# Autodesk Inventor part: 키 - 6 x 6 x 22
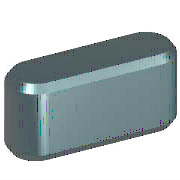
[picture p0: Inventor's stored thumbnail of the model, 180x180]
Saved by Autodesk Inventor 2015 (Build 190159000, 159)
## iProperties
IsCustomPart: 1
Created: 2012-02
Part Number: 키 - 6 x 6 x 22
Material: 강철, 연강
Description: 키 및 해당 키홈
Document SubType Name: Modeling
Standard: KS B 1311
Designer: mduedu
Standards Organization: KS
Language: ko-KR
Size Designation: 6 x 6 x 22
Categories: <MemberInstance><Categories><Category DisplayName="샤프트 부품" InternalName="7f7aeb1f-a693-4053-b835-cee3144e0d98" Mnemonic="SHFT"><Category DisplayName="키" Interna
Density: 7.86 g/cm^3
Mass: 5.79788 g
Surface Area: 5.294 cm^2
Volume: 0.737644 cm^3
Appearance: 노란색
Author: mduedu
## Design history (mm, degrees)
workplane "Work Plane1"
workplane "Work Plane2"
sketch "스케치1"
  geometry: L1 (3, 3)-(19, 3); L2 (19, -3)-(3, -3); L3 (0, 9.4)-(0, -7.4) reference; L4 (-5, 0)-(30, 0) reference; L5 (22, 0)-(22, 7); A1 r 3 centre (3, 0) between (3, 3) and (3, -3); A2 r 3 centre (19, 0) between (19, -3) and (19, 3)
  constraints: 6 end point, 5 point on circle, 4 tangent, 3 point on line, 2 centre point, 1 horizontal, 1 parallel, 1 perpendicular
  dimensions: "d0" = 3 radius of A1 (= 0.5 x PB); "d13" = 3 radius of A2 (= 0.5 x PB); "d14" = 22 distance between parallel lines of L5 L3 (= NLG)
extrude "본체1" new body sketch "스케치1" taper "d3" = 0 deg; stored distance "d4" = 10
workplane "Work Plane3"
body "Solid1"
chamfer "모따기1" distance "d8" = 0.4 (= PHH); stored, may be unused: second distance "d9" = 0.4 (= PHH), angle "d15" = 45 deg
other parameters: "d1" = -3.5 (= -PNT), "d2" = 2.5 (= PH - PNT), "NLG" = 22 [user parameter; used in 3 equation terms], "PB" = 6 [user parameter; used in 2 equation terms], "PNT" = 3.5 [user parameter; used in 2 equation terms], "PH" = 6 [user parameter; used in 1 equation term], "PHH" = 0.4 [user parameter; used in 2 equation terms], "d10" = 0, "d16" = 0, "d17" = 0, "d18" = 0, "WDMIN" = 17 [user parameter], "PLB2" = 22 (= NLG) [user parameter], "WDMAX" = 22 [user parameter], "PLB1" = 22 (= NLG) [user parameter], "RR" = 0.16 [user parameter], "PUEB" = 2.8 [user parameter]
